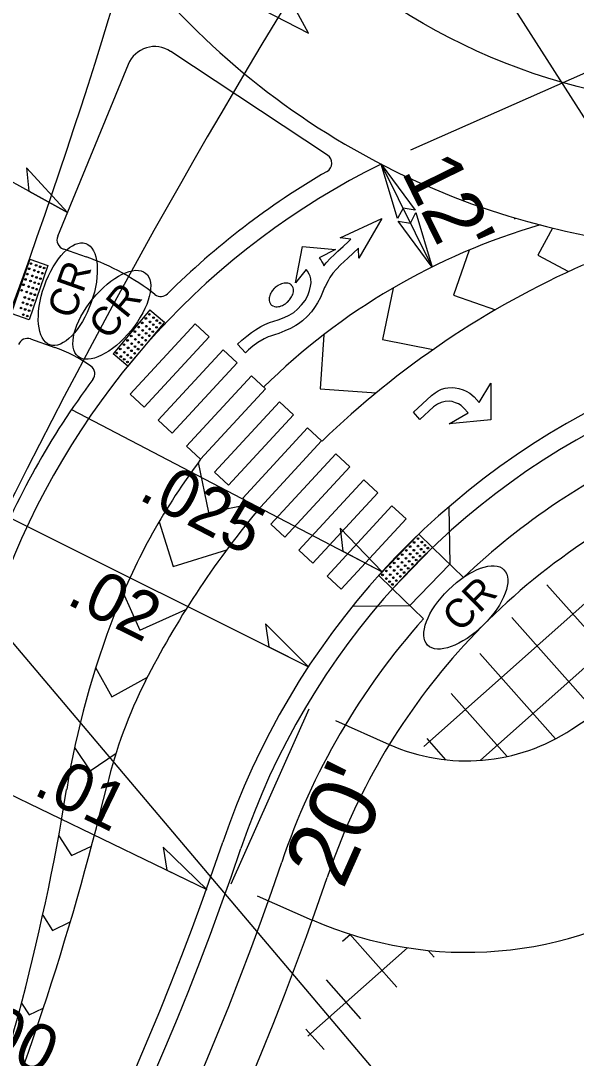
# Model space of a CAD drawing. Extents: x 2010838 to 2015151, y 441905 to 447792.
# Drawn here: x 2011893.1 to 2011951.1, y 444822.7 to 444931.1 of the extents above; entities that cross this region are included whole.
import ezdxf

# ---------------------------------------------------------------- set-up
doc = ezdxf.new("R2010")
doc.units = 0
for name, color, linetype in [('A-Wall-Abov', 7, 'Continuous'), ('A-Wall-Blow', 7, 'Continuous'), ('A-Wall-Comp', 7, 'Continuous'), ('B-Sheet Number', 7, 'Continuous'), ('C - EC', 7, 'Continuous'), ('C-Alignment Geometry', 7, 'Continuous'), ('C-CURB STOPS', 7, 'Continuous'), ('C-Grave Plots', 7, 'Continuous'), ('C-Surface', 7, 'Continuous'), ('CLRD', 7, 'Continuous'), ('Default_10ft_LIDAR_Contou', 7, 'Continuous'), ('HATCH', 7, 'Continuous'), ('s-Existing Major', 7, 'Continuous'), ('S-Existing Minor', 7, 'Continuous'), ('S-overhead electric', 7, 'Continuous'), ('TEXT-LG', 7, 'Continuous'), ('TEXT-MED', 7, 'Continuous'), ('X2', 7, 'Continuous'), ('X4', 7, 'Continuous')]:
    doc.layers.add(name, color=color, linetype=linetype)

msp = doc.modelspace()

# ---------------------------------------------------------------- linework, layer by layer
at = {"layer": 'A-Wall-Abov'}
for points in [[(2011920.61, 444934.46), (2011920.57, 444932.99), (2011916.76, 444936.71), (2011916.06, 444936), (2011919.87, 444932.27), (2011918.4, 444932.2), (2011923.13, 444929.78)], [(2011930.79, 444910.43), (2011928.4, 444906.28), (2011928.36, 444907.31), (2011927.8, 444906.79), (2011927.24, 444906.27), (2011926.49, 444905.56), (2011926.06, 444905.12), (2011925.69, 444904.7), (2011925.38, 444904.26), (2011925.18, 444903.92), (2011924.88, 444903.31), (2011924.81, 444903.19), (2011924.39, 444902.16), (2011924.09, 444901.61), (2011923.78, 444901.11), (2011923.46, 444900.68), (2011923.02, 444900.2), (2011922.5, 444899.72), (2011922.09, 444899.42), (2011921.82, 444899.24), (2011921.25, 444898.94), (2011920.66, 444898.67), (2011920.05, 444898.42), (2011919.59, 444898.26), (2011919.17, 444898.14), (2011918.91, 444898.07), (2011918.51, 444897.86), (2011917.85, 444897.46), (2011917.31, 444897.07), (2011916.86, 444896.69), (2011916.54, 444896.38), (2011915.71, 444897.28), (2011916.18, 444897.69), (2011916.69, 444898.11), (2011917.19, 444898.51), (2011917.6, 444898.8), (2011918.16, 444899.14), (2011918.59, 444899.35), (2011919.08, 444899.55), (2011919.51, 444899.68), (2011919.96, 444899.82), (2011920.61, 444900.08), (2011921.13, 444900.33), (2011921.59, 444900.61), (2011921.98, 444900.94), (2011922.42, 444901.39), (2011922.78, 444901.86), (2011923.07, 444902.38), (2011923.24, 444902.88), (2011923.35, 444903.33), (2011923.4, 444903.69), (2011923.38, 444904.11), (2011923.31, 444904.38), (2011923.22, 444904.61), (2011923.04, 444904.92), (2011922.91, 444905.1), (2011921.77, 444903.68), (2011922.52, 444907.5), (2011925.95, 444907.17), (2011924.24, 444906.3), (2011924.41, 444906.09), (2011924.54, 444905.9), (2011924.66, 444905.69), (2011924.74, 444905.48), (2011924.99, 444905.77), (2011925.45, 444906.26), (2011925.82, 444906.63), (2011926.21, 444906.99), (2011926.75, 444907.49), (2011927.32, 444908.02), (2011927.56, 444908.25), (2011926.46, 444908.38)], [(2011934.78, 444889.43), (2011934.1, 444890.17), (2011935.99, 444891.92), (2011936.36, 444892.22), (2011936.67, 444892.42), (2011937.04, 444892.6), (2011937.4, 444892.7), (2011937.71, 444892.74), (2011938.14, 444892.76), (2011938.47, 444892.72), (2011938.85, 444892.66), (2011939.29, 444892.53), (2011939.6, 444892.39), (2011939.98, 444892.16), (2011940.43, 444891.79), (2011940.98, 444891.2), (2011942.18, 444893.21), (2011942.2, 444889.38), (2011937.82, 444888.96), (2011939.82, 444890.12), (2011939.36, 444890.61), (2011939.09, 444890.87), (2011938.79, 444891.06), (2011938.51, 444891.17), (2011938.13, 444891.29), (2011937.83, 444891.33), (2011937.41, 444891.3), (2011937, 444891.19), (2011936.63, 444891.03), (2011936.18, 444890.73)], [(2011934.78, 444889.43), (2011934.1, 444890.17), (2011935.99, 444891.92), (2011936.36, 444892.22), (2011936.67, 444892.42), (2011937.04, 444892.6), (2011937.4, 444892.7), (2011937.71, 444892.74), (2011938.14, 444892.76), (2011938.47, 444892.72), (2011938.85, 444892.66), (2011939.29, 444892.53), (2011939.6, 444892.39), (2011939.98, 444892.16), (2011940.43, 444891.79), (2011940.98, 444891.2), (2011942.18, 444893.21), (2011942.2, 444889.38), (2011937.82, 444888.96), (2011939.82, 444890.12), (2011939.36, 444890.61), (2011939.09, 444890.87), (2011938.79, 444891.06), (2011938.51, 444891.17), (2011938.13, 444891.29), (2011937.83, 444891.33), (2011937.41, 444891.3), (2011937, 444891.19), (2011936.63, 444891.03), (2011936.18, 444890.73)]]:
    msp.add_lwpolyline(points, close=True, dxfattribs=at)
for centre, radius, start, end in [((2011921.05, 444901.62), 2.1, 134.8164, 147.5156), ((2011920.96, 444901.71), 1.98, 132.7778, 134.8164), ((2011920.96, 444901.71), 1.98, 130.7393, 132.7778), ((2011921.04, 444901.62), 2.1, 118.0401, 130.7393), ((2011921, 444901.7), 2.01, 110.0553, 118.0401), ((2011920.79, 444902.27), 1.4, 87.3258, 110.0553), ((2011920.82, 444902.9), 0.777, 67.1248, 87.3258), ((2011920.83, 444902.93), 0.742, 44.0113, 67.1248), ((2011920.92, 444903.02), 0.613, 42.7778, 44.0113), ((2011920.92, 444903.02), 0.613, 41.5444, 42.7778), ((2011920.82, 444902.93), 0.742, 18.4309, 41.5444), ((2011920.17, 444902.94), 1.4, 335.5004, 358.2299), ((2011920.79, 444902.92), 0.777, 358.2299, 18.4309), ((2011920.41, 444901.93), 1.4, 155.5004, 178.2299), ((2011919.79, 444901.95), 0.777, 178.2299, 198.4309), ((2011920.97, 444901.67), 2.01, 147.5156, 155.5004), ((2011919.62, 444903.16), 1.98, 312.7778, 314.8164), ((2011919.53, 444903.24), 2.1, 314.8164, 327.5156), ((2011919.61, 444903.19), 2.01, 327.5156, 335.5004), ((2011919.76, 444901.94), 0.742, 198.4309, 221.5444), ((2011919.66, 444901.85), 0.613, 221.5444, 222.7778), ((2011919.66, 444901.85), 0.613, 222.7778, 224.0113), ((2011919.75, 444901.94), 0.742, 224.0113, 247.1248), ((2011919.77, 444901.97), 0.777, 247.1248, 267.3258), ((2011919.8, 444902.59), 1.4, 267.3258, 290.0553), ((2011919.59, 444903.17), 2.01, 290.0553, 298.0401), ((2011919.54, 444903.25), 2.1, 298.0401, 310.7393), ((2011919.62, 444903.16), 1.98, 310.7393, 312.7778)]:
    msp.add_arc(centre, radius, start, end, dxfattribs=at)
at = {"layer": 'A-Wall-Blow'}
for p, q in [((2011897.95, 444911.04), (2011870.53, 444926.22)), ((2011898.38, 444890.45), (2011930.83, 444873.52)), ((2011891.96, 444879.15), (2011923.13, 444863.6)), ((2011884.23, 444854.02), (2011912.5, 444840.34))]:
    msp.add_line(p, q, dxfattribs=at)
at = {"layer": 'A-Wall-Comp'}
for points in [[(2011897.95, 444911.04), (2011893.67, 444915.69), (2011893.91, 444913.28)], [(2011930.83, 444873.52), (2011926.43, 444878.07), (2011926.73, 444875.66)], [(2011923.13, 444863.6), (2011918.65, 444868.07), (2011918.99, 444865.67)], [(2011912.5, 444840.34), (2011907.97, 444844.75), (2011908.34, 444842.35)]]:
    msp.add_lwpolyline(points, close=True, dxfattribs=at)
at = {"layer": 'B-Sheet Number'}
for p, q in [((2011925.95, 444857.98), (2011931.58, 444855.47)), ((2011917.77, 444839.68), (2011923.53, 444837.12))]:
    msp.add_line(p, q, dxfattribs=at)
at = {"layer": 'C - EC'}
for p, q in [((2011941.09, 444853.83), (2011979.92, 444888.34)), ((2011935.2, 444855.28), (2011964.9, 444881.67)), ((2011957.45, 444861.56), (2011948.04, 444872.14)), ((2011953.23, 444858.77), (2011944.37, 444868.74)), ((2011948.94, 444856.07), (2011941.04, 444864.97)), ((2011943.89, 444854.23), (2011938.04, 444860.81)), ((2011937.5, 444853.89), (2011935.54, 444856.1)), ((2011926.69, 444834.92), (2011927.52, 444835.65)), ((2011932.36, 444830.14), (2011927.42, 444835.69)), ((2011923.08, 444825.01), (2011933.47, 444834.25)), ((2011936.28, 444833.25), (2011935.63, 444833.97)), ((2011928.62, 444826.82), (2011925.01, 444830.88)), ((2011924.78, 444823.61), (2011922.87, 444825.76))]:
    msp.add_line(p, q, dxfattribs=at)
at = {"layer": 'C-Alignment Geometry'}
for p, q in [((2011948.61, 444909.42), (2011947.11, 444906.58)), ((2011939.93, 444907.11), (2011938.29, 444902.42)), ((2011947.11, 444906.58), (2011950.31, 444904.88)), ((2011931.97, 444903.14), (2011930.88, 444897.79)), ((2011938.29, 444902.42), (2011942.67, 444900.89)), ((2011924.74, 444898.28), (2011924.35, 444892.62)), ((2011930.88, 444897.79), (2011936.15, 444896.72)), ((2011924.35, 444892.62), (2011930.2, 444892.21)), ((2011911.62, 444884.92), (2011912.69, 444879.69)), ((2011912.69, 444879.69), (2011916.95, 444880.57)), ((2011907.53, 444878.72), (2011909.01, 444874.05)), ((2011909.01, 444874.05), (2011914.6, 444875.82)), ((2011903.78, 444871.3), (2011905.51, 444867.42)), ((2011905.51, 444867.42), (2011910.32, 444869.57)), ((2011900.9, 444863.51), (2011902.59, 444860.46)), ((2011902.59, 444860.46), (2011906.32, 444862.52)), ((2011898.7, 444855.15), (2011900.34, 444852.74)), ((2011900.34, 444852.74), (2011903.03, 444854.57)), ((2011897.04, 444845.92), (2011898.37, 444843.87)), ((2011898.37, 444843.87), (2011900.47, 444844.87)), ((2011895.37, 444837.64), (2011896.4, 444836.06)), ((2011896.4, 444836.06), (2011898.25, 444836.94)), ((2011893.16, 444828.45), (2011893.95, 444827.23)), ((2011893.95, 444827.23), (2011895.43, 444827.93))]:
    msp.add_line(p, q, dxfattribs=at)
for centre, radius, start, end in [((2011966.23, 444844.41), 68, 106.1206, 134.6366), ((2011989.97, 444819.65), 94, 113.9163, 134.0999), ((2011966.23, 444844.41), 68, 143.0732, 158.6236), ((2011989.97, 444819.65), 94, 140.1981, 153.1683), ((2011986.72, 444836.39), 90, 158.6236, 170.8051), ((2011951.01, 444839.37), 50.33, 153.1683, 166.3627), ((2011610.55, 444921.96), 300, 327.6618, 346.3627), ((2011662.93, 444888.8), 238, 327.6618, 350.8051)]:
    msp.add_arc(centre, radius, start, end, dxfattribs=at)
at = {"layer": 'C-CURB STOPS'}
for p, q in [((2011925.13, 444917.03), (2011908.74, 444927.87)), ((2011904.31, 444926.51), (2011896.93, 444908.55)), ((2011897.53, 444907.23), (2011899.92, 444906.4)), ((2011894.11, 444897.83), (2011896.63, 444896.95))]:
    msp.add_line(p, q, dxfattribs=at)
for centre, radius, start, end in [((2011907.08, 444925.37), 3, 56.5251, 157.6723), ((2011924.58, 444916.2), 1, 300.1214, 56.5251), ((2011966.23, 444844.41), 82, 120.1214, 134.8334), ((2011897.86, 444908.17), 1, 157.6723, 250.782), ((2011891.69, 444882.79), 25, 51.9609, 70.782), ((2011907.71, 444903.27), 1, 231.9609, 314.8334), ((2011893.78, 444896.89), 1, 70.782, 159.5904), ((2011891.69, 444882.79), 15, 54.5141, 70.782), ((2011899.82, 444894.19), 1, 323.1452, 54.5141), ((2011966.23, 444844.41), 82, 143.1452, 158.6236)]:
    msp.add_arc(centre, radius, start, end, dxfattribs=at)
at = {"layer": 'C-Surface'}
msp.add_line((2011987.73, 444941.46), (2011933.8, 444917.54), dxfattribs=at)
at = {"layer": 'CLRD'}
msp.add_arc((2012535.6, 444558.07), 720, 139.84446, 154.1777, dxfattribs=at)
at = {"layer": 'Default_10ft_LIDAR_Contou'}
for p, q in [((2012044.12, 444776.47), (2011932.53, 444951.39)), ((2011887.5, 444871.69), (2011991.38, 444748.94))]:
    msp.add_line(p, q, dxfattribs=at)
at = {"layer": 'HATCH'}
for p, q in [((2011930.73, 444916.1), (2011936.05, 444905.34)), ((2011944.67, 444910.39), (2011944.81, 444910.44)), ((2011911.29, 444899.41), (2011904.5, 444892.07)), ((2011912.76, 444898.06), (2011911.29, 444899.41)), ((2011905.97, 444890.71), (2011912.76, 444898.06)), ((2011914.23, 444896.7), (2011907.44, 444889.35)), ((2011915.7, 444895.34), (2011914.23, 444896.7)), ((2011908.91, 444888), (2011915.7, 444895.34)), ((2011917.17, 444893.98), (2011910.38, 444886.64)), ((2011918.63, 444892.63), (2011917.17, 444893.98)), ((2011904.5, 444892.07), (2011905.97, 444890.71)), ((2011911.85, 444885.28), (2011918.63, 444892.63)), ((2011920.1, 444891.27), (2011913.32, 444883.92)), ((2011921.57, 444889.91), (2011920.1, 444891.27)), ((2011914.79, 444882.57), (2011921.57, 444889.91)), ((2011907.44, 444889.35), (2011908.91, 444888)), ((2011923.04, 444888.56), (2011916.26, 444881.21)), ((2011924.51, 444887.2), (2011923.04, 444888.56)), ((2011910.38, 444886.64), (2011911.85, 444885.28)), ((2011917.73, 444879.85), (2011924.51, 444887.2)), ((2011925.98, 444885.84), (2011919.2, 444878.5)), ((2011927.45, 444884.49), (2011925.98, 444885.84)), ((2011920.67, 444877.14), (2011927.45, 444884.49)), ((2011913.32, 444883.92), (2011914.79, 444882.57)), ((2011928.92, 444883.13), (2011922.13, 444875.78)), ((2011930.39, 444881.77), (2011928.92, 444883.13)), ((2011916.26, 444881.21), (2011917.73, 444879.85)), ((2011923.6, 444874.43), (2011930.39, 444881.77)), ((2011931.86, 444880.42), (2011925.07, 444873.07)), ((2011933.33, 444879.06), (2011931.86, 444880.42)), ((2011926.54, 444871.71), (2011933.33, 444879.06)), ((2011919.2, 444878.5), (2011920.67, 444877.14)), ((2011922.13, 444875.78), (2011923.6, 444874.43)), ((2011925.07, 444873.07), (2011926.54, 444871.71))]:
    msp.add_line(p, q, dxfattribs=at)
msp.add_circle((2011967.46, 444987.16), 65, dxfattribs=at)
msp.add_arc((2011967.46, 444987.16), 80, 242.6645, 336.5135, dxfattribs=at)
at = {"layer": 's-Existing Major'}
for points in [[(2011932.42, 444910.41), (2011930.73, 444916.1), (2011934.27, 444911.29), (2011933.01, 444911.49)], [(2011934.36, 444911.03), (2011936.05, 444905.34), (2011932.51, 444910.15), (2011933.78, 444909.94)]]:
    msp.add_lwpolyline(points, close=True, dxfattribs=at)
at = {"layer": 'S-Existing Minor'}
msp.add_line((2011930.73, 444916.1), (2011936.05, 444905.34), dxfattribs=at)
at = {"layer": 'S-overhead electric'}
msp.add_line((2011950.65, 444857.08), (2011993.25, 444885.16), dxfattribs=at)
for centre, radius, start, end in [((2011328.64, 445107.17), 600, 314.56735, 343.62875), ((2011967.46, 444987.16), 80, 217.8699, 242.6645), ((2011966.23, 444844.41), 80, 116.3467, 158.6236), ((2011989.97, 444819.65), 80, 113.9163, 161.328), ((2011939.64, 444873.77), 20, 246.2263, 303.397), ((2011629.97, 444941.31), 300, 303.2131, 341.328), ((2011939.64, 444873.77), 40, 246.2263, 303.397)]:
    msp.add_arc(centre, radius, start, end, dxfattribs=at)
at = {"layer": 'TEXT-LG'}
for p, q in [((2011894.04, 444906.15), (2011892.06, 444900.49)), ((2011894.04, 444906.15), (2011895.92, 444905.5)), ((2011895.92, 444905.5), (2011893.95, 444899.83)), ((2011906.57, 444900.87), (2011902.72, 444896.27)), ((2011906.57, 444900.87), (2011908.1, 444899.59)), ((2011893.95, 444899.83), (2011892.06, 444900.49)), ((2011908.1, 444899.59), (2011904.25, 444894.99)), ((2011904.25, 444894.99), (2011902.72, 444896.27)), ((2011937.79, 444880.3), (2011937.89, 444874.31)), ((2011934.65, 444877.45), (2011930.48, 444873.14)), ((2011934.65, 444877.45), (2011936.09, 444876.05)), ((2011936.09, 444876.05), (2011931.91, 444871.75)), ((2011936.09, 444876.05), (2011939.32, 444872.92)), ((2011933.71, 444870), (2011937.89, 444874.31)), ((2011931.91, 444871.75), (2011930.48, 444873.14)), ((2011931.91, 444871.74), (2011935.15, 444868.61)), ((2011927.73, 444869.91), (2011933.71, 444870))]:
    msp.add_line(p, q, dxfattribs=at)
for centre in [(2011893.96, 444905.16), (2011894.15, 444905.7), (2011894.49, 444904.99), (2011894.68, 444905.53), (2011895.11, 444905.37), (2011895.52, 444905.24), (2011893.57, 444904.05), (2011893.76, 444904.6), (2011894.1, 444903.88), (2011894.29, 444904.42), (2011894.72, 444904.26), (2011894.92, 444904.83), (2011895.13, 444904.13), (2011895.33, 444904.7), (2011893.17, 444902.91), (2011893.37, 444903.49), (2011893.7, 444902.74), (2011893.9, 444903.31), (2011894.33, 444903.16), (2011894.53, 444903.72), (2011894.74, 444903.03), (2011894.94, 444903.59), (2011893.5, 444902.17), (2011893.93, 444902.02), (2011894.13, 444902.58), (2011894.34, 444901.88), (2011894.54, 444902.45), (2011893.11, 444901.06), (2011893.31, 444901.63), (2011893.54, 444900.91), (2011893.74, 444901.47), (2011893.95, 444900.78), (2011894.15, 444901.34), (2011893.35, 444900.37), (2011893.76, 444900.23), (2011905.76, 444899.51), (2011906.15, 444899.97), (2011906.51, 444900.41), (2011906.58, 444899.62), (2011906.95, 444900.06), (2011907.29, 444899.76), (2011907.63, 444899.49), (2011905, 444898.61), (2011905.39, 444899.07), (2011905.82, 444898.72), (2011906.17, 444898.42), (2011906.19, 444899.16), (2011906.54, 444898.86), (2011906.87, 444898.59), (2011906.92, 444899.32), (2011907.26, 444899.05), (2011904.23, 444897.68), (2011904.62, 444898.14), (2011904.66, 444897.34), (2011905.05, 444897.79), (2011905.39, 444897.49), (2011905.43, 444898.26), (2011905.78, 444897.96), (2011906.12, 444897.7), (2011906.51, 444898.16), (2011903.1, 444896.35), (2011903.47, 444896.79), (2011903.86, 444897.24), (2011903.9, 444896.44), (2011904.29, 444896.9), (2011904.64, 444896.6), (2011904.97, 444896.33), (2011905.01, 444897.04), (2011905.34, 444896.77), (2011905.73, 444897.23), (2011903.53, 444896), (2011903.88, 444895.7), (2011904.22, 444895.43), (2011904.25, 444896.14), (2011904.59, 444895.87), (2011934.57, 444876.99), (2011933.35, 444875.74), (2011933.75, 444876.15), (2011934.15, 444875.77), (2011934.17, 444876.58), (2011934.57, 444876.2), (2011934.9, 444875.87), (2011934.97, 444876.61), (2011935.3, 444876.28), (2011935.61, 444875.99), (2011932.51, 444874.87), (2011932.93, 444875.31), (2011933.33, 444874.93), (2011933.66, 444874.6), (2011933.75, 444875.36), (2011934.08, 444875.03), (2011934.39, 444874.74), (2011934.48, 444875.44), (2011934.79, 444875.15), (2011935.21, 444875.58), (2011931.27, 444873.6), (2011931.69, 444874.03), (2011932.09, 444874.44), (2011932.09, 444873.65), (2011932.49, 444874.06), (2011932.82, 444873.73), (2011932.91, 444874.49), (2011933.24, 444874.16), (2011933.55, 444873.87), (2011933.98, 444874.31), (2011930.87, 444873.19), (2011931.27, 444872.81), (2011931.6, 444872.48), (2011931.67, 444873.22), (2011932, 444872.89), (2011932.31, 444872.6), (2011932.42, 444873.32), (2011932.73, 444873.03), (2011933.13, 444873.44), (2011931.91, 444872.19)]:
    msp.add_circle(centre, 0.0869, dxfattribs=at)
for centre, radius, start, end in [((2011989.97, 444819.65), 73.5, 113.9163, 133.5582), ((2011989.97, 444819.65), 68.5, 113.9163, 138.4074), ((2011989.97, 444819.65), 73.5, 138.2363, 161.328), ((2011989.97, 444819.65), 68.5, 138.4074, 161.328), ((2011629.97, 444941.31), 306.5, 303.2131, 341.328), ((2011629.97, 444941.31), 311.5, 303.2131, 341.328)]:
    msp.add_arc(centre, radius, start, end, dxfattribs=at)
at = {"layer": 'TEXT-MED'}
for centre, radius, start, end in [((2011989.97, 444819.65), 78, 113.9163, 161.328), ((2011629.97, 444941.31), 302, 303.2131, 341.328)]:
    msp.add_arc(centre, radius, start, end, dxfattribs=at)
at = {"layer": 'X2'}
msp.add_line((2011923.16, 444859.17), (2011915.03, 444840.9), dxfattribs=at)
at = {"layer": 'X4'}
for centre, major_axis in [((2011897.99, 444902.51), (1.87, 5.29)), ((2011902.59, 444900.36), (3.53, 4.35)), ((2011939.57, 444869.79), (3.99, 3.94))]:
    msp.add_ellipse(centre, major_axis=major_axis, ratio=0.462467, dxfattribs=at)

# ---------------------------------------------------------------- texts
at = {"layer": 'A-Wall-Blow'}
for s, rotation, p in [('.025', 332.4532, (2011905.24, 444881.16)), ('.02', 333.4877, (2011897.7, 444870.24)), ('.01', 334.1777, (2011894.24, 444850.33)), ('.00', 334.1777, (2011887, 444824.83))]:
    msp.add_text(s, height=5, rotation=rotation, dxfattribs=at).set_placement(p)
at = {"layer": 'C-Grave Plots'}
for s, height, rotation, p in [("12'", 6, 296.3467, (2011932.79, 444915.33)), ("20'", 7, 65.9954, (2011926.73, 444840.22))]:
    msp.add_text(s, height=height, rotation=rotation, dxfattribs=at).set_placement(p)
at = {"layer": 'X4'}
for rotation, p in [(70.5586, (2011898.6, 444899.8)), (50.9386, (2011902.25, 444897.6)), (44.5933, (2011938.93, 444867.08))]:
    msp.add_text('CR', height=3, rotation=rotation, dxfattribs=at).set_placement(p)

doc.saveas('drawing.dxf')
